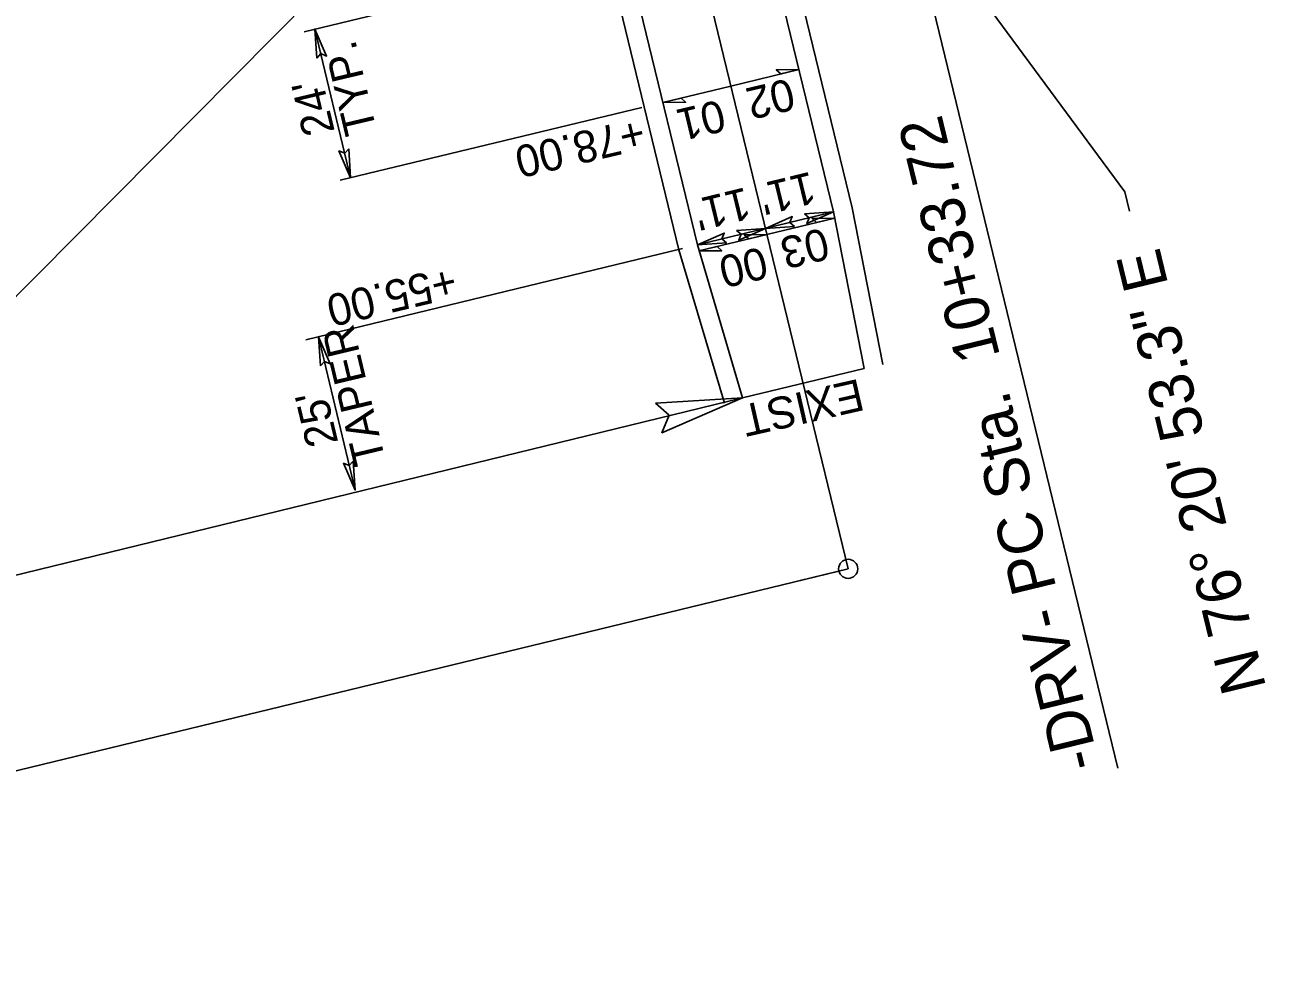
# Model space of a CAD drawing. Extents: x 1735795 to 1737428, y 699740 to 701024.
# Drawn here: x 1736155.8 to 1736350.4, y 700129.9 to 700280.2 of the extents above; entities that cross this region are included whole.
import ezdxf

# ---------------------------------------------------------------- set-up
doc = ezdxf.new("R2010")
doc.units = 0
for name, color, linetype in [('Prop Dimension', 7, 'Continuous'), ('Prop Dimension Text', 7, 'Continuous'), ('Prop EOT', 7, 'Continuous'), ('Prop Horizontal Alignment', 7, 'Continuous'), ('Prop Horizontal Alignment Direction Label', 7, 'Continuous'), ('Prop Horizontal Alignment Station Label', 7, 'Continuous'), ('Prop Horizontal Alignment Tick Large', 7, 'Continuous'), ('Prop Leader Line Heavy', 7, 'Continuous'), ('Prop Superelevation  Arrow CELL', 7, 'Continuous'), ('Prop Terminator CELL', 7, 'Continuous'), ('Scratch_Level_2', 7, 'Continuous')]:
    doc.layers.add(name, color=color, linetype=linetype)

msp = doc.modelspace()

# ---------------------------------------------------------------- linework, layer by layer
at = {"layer": 'Prop Dimension'}
for p, q in [((1736246.97, 700290.6), (1736199.63, 700279.17)), ((1736252.6, 700267.27), (1736205.27, 700255.84)), ((1736261.3, 700245.69), (1736282.68, 700250.88)), ((1736258.98, 700245.13), (1736199.87, 700230.77)), ((1736207.61, 700207.2), (1736201.87, 700231.26))]:
    msp.add_line(p, q, dxfattribs=at)
at = {"layer": 'Prop EOT'}
for p, q in [((1736261.3, 700245.69), (1736190.12, 700538.78)), ((1736282.68, 700250.88), (1736266.33, 700318.22)), ((1736282.68, 700250.88), (1736287.45, 700226.31)), ((1736268.41, 700221.69), (1736261.3, 700245.69)), ((1736287.45, 700226.31), (1736268.41, 700221.69))]:
    msp.add_line(p, q, dxfattribs=at)
at = {"layer": 'Prop Horizontal Alignment'}
msp.add_line((1736284.97, 700194.84), (1736200.81, 700541.38), dxfattribs=at)
at = {"layer": 'Prop Horizontal Alignment Station Label'}
for p, q in [((1736284.04, 700341.56), (1736327.27, 700163.56)), ((1736250.92, 700335.06), (1736104.01, 700186.73)), ((1736328.39, 700254.01), (1736298.63, 700294.32)), ((1736329.11, 700250.99), (1736328.39, 700254.01)), ((1736283.52, 700194.49), (1736017.74, 700129.94))]:
    msp.add_line(p, q, dxfattribs=at)
msp.add_circle((1736284.97, 700194.84), 1.5, dxfattribs=at)
at = {"layer": 'Prop Horizontal Alignment Tick Large'}
msp.add_line((1736284.97, 700194.84), (1736277.2, 700192.95), dxfattribs=at)
at = {"layer": 'Prop Leader Line Heavy'}
msp.add_line((1736268.39, 700221.7), (1735960.42, 700146.42), dxfattribs=at)
at = {"layer": 'Prop Superelevation  Arrow CELL'}
for p, q in [((1736201.28, 700279.57), (1736206.89, 700256.23)), ((1736277.26, 700273.22), (1736266.57, 700270.64)), ((1736266.57, 700270.64), (1736255.87, 700268.06)), ((1736282.89, 700249.89), (1736272.2, 700247.31)), ((1736272.23, 700247.32), (1736261.54, 700244.74))]:
    msp.add_line(p, q, dxfattribs=at)
for points in [[(1736277.26, 700273.22), (1736273.67, 700273.19), (1736274.39, 700272.54)], [(1736255.87, 700268.06), (1736259.46, 700268.09), (1736258.74, 700268.74)], [(1736282.89, 700249.89), (1736279.3, 700249.86), (1736280.02, 700249.21)], [(1736272.23, 700247.32), (1736268.64, 700247.28), (1736269.36, 700246.63)], [(1736261.54, 700244.74), (1736265.13, 700244.77), (1736264.41, 700245.42)]]:
    msp.add_lwpolyline(points, close=True, dxfattribs=at)
at = {"layer": 'Prop Terminator CELL'}
for points in [[(1736201.58, 700275.01), (1736201.28, 700279.57), (1736203.12, 700275.35), (1736202.21, 700275.73)], [(1736206.59, 700260.79), (1736206.89, 700256.23), (1736205.05, 700260.44), (1736205.97, 700260.07)], [(1736278.13, 700250.58), (1736282.68, 700250.88), (1736278.47, 700249.04), (1736278.84, 700249.95)], [(1736276.55, 700248.6), (1736271.99, 700248.29), (1736276.2, 700250.13), (1736275.83, 700249.22)], [(1736265.86, 700246), (1736261.3, 700245.69), (1736265.51, 700247.54), (1736265.14, 700246.62)], [(1736267.44, 700247.98), (1736271.99, 700248.29), (1736267.79, 700246.44), (1736268.16, 700247.36)], [(1736202.16, 700226.7), (1736201.87, 700231.26), (1736203.69, 700227.04), (1736202.78, 700227.41)], [(1736254.72, 700220.83), (1736268.39, 700221.7), (1736255.74, 700216.21), (1736256.86, 700218.95)], [(1736207.31, 700211.75), (1736207.61, 700207.2), (1736205.78, 700211.41), (1736206.69, 700211.04)]]:
    msp.add_lwpolyline(points, close=True, dxfattribs=at)
at = {"layer": 'Scratch_Level_2'}
for p, q in [((1736285.61, 700251.52), (1736267.37, 700326.64)), ((1736258.41, 700244.91), (1736242.33, 700311.09)), ((1736285.61, 700251.52), (1736290.39, 700226.89)), ((1736265.54, 700220.84), (1736258.41, 700244.91))]:
    msp.add_line(p, q, dxfattribs=at)

# ---------------------------------------------------------------- texts
at = {"layer": 'Prop Dimension Text'}
for s, rotation, p in [("11'", 193.6519, (1736279.11, 700257.23)), ("11'", 193.6519, (1736268.88, 700254.77)), ('+55.00', 193.4184, (1736222.85, 700242.44)), ('TAPER', 103.4184, (1736212.41, 700211.79)), ("25'", 103.4184, (1736204.98, 700214.66))]:
    msp.add_text(s, height=5, rotation=rotation, dxfattribs=at).set_placement(p)
at = {"layer": 'Prop Horizontal Alignment Direction Label'}
msp.add_text('N 76%%d 20\' 53.3" E', height=7, rotation=103.6519, dxfattribs=at).set_placement((1736350.58, 700176.19))
at = {"layer": 'Prop Horizontal Alignment Station Label'}
msp.add_text('-DRV- PC Sta.  10+33.72', height=7, rotation=103.6519, dxfattribs=at).set_placement((1736324.42, 700164))
at = {"layer": 'Prop Superelevation  Arrow CELL'}
for s, rotation, p in [('TYP.', 103.3409, (1736211.01, 700263.63)), ("24'", 103.3409, (1736204.43, 700263.5)), ('02', 193.4103, (1736275.82, 700271.9)), ('01', 193.4103, (1736264.94, 700268.55)), ('+78.00', 193.3409, (1736252.4, 700265.76)), ('03', 193.4103, (1736281.22, 700248.43)), ('00', 193.4103, (1736271.57, 700245.45)), ('EXIST', 192.8139, (1736286.69, 700224.71))]:
    msp.add_text(s, height=5, rotation=rotation, dxfattribs=at).set_placement(p)

doc.saveas('drawing.dxf')
